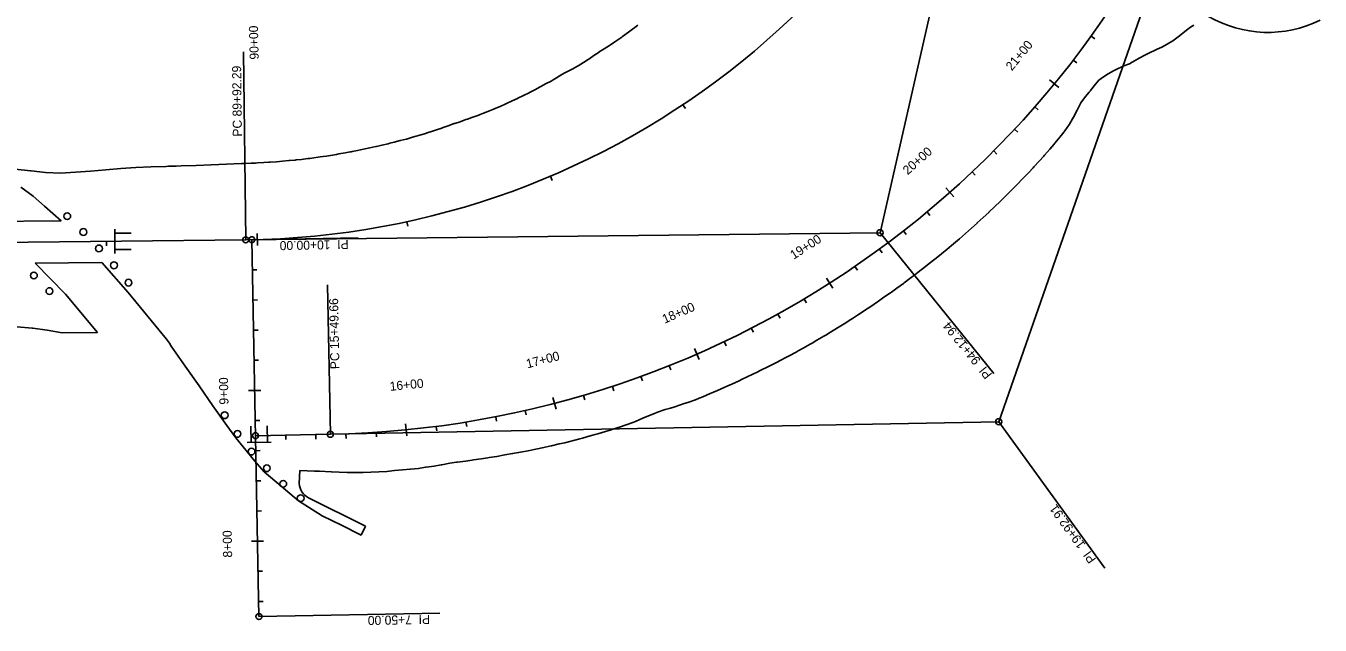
# Model space of a CAD drawing. Extents: x 1710760 to 1712674, y 548603 to 551129.
# Drawn here: x 1711587 to 1712445, y 548957 to 549354 of the extents above; entities that cross this region are included whole.
import ezdxf

# ---------------------------------------------------------------- set-up
doc = ezdxf.new("R2010")
doc.units = 0
for name, color, linetype in [('R_Horz Alg', 7, 'Continuous'), ('R_Horz Alg Annot', 7, 'Continuous'), ('R_MOT', 7, 'Continuous')]:
    doc.layers.add(name, color=color, linetype=linetype)

msp = doc.modelspace()

# ---------------------------------------------------------------- linework, layer by layer
at = {"layer": 'R_Horz Alg'}
for p, q in [((1711391.77, 549208.53), (1711733, 549212.35)), ((1711391.77, 549208.53), (1711733, 549212.35)), ((1711741.76, 548962.46), (1711737.05, 549212.41)), ((1711739.5, 549082.44), (1711789.16, 549083.37))]:
    msp.add_line(p, q, dxfattribs=at)
for centre, radius, start, end in [((1711727.02, 549745.3), 532.98, 270.64281, 347.20664), ((1711727.02, 549745.3), 532.98, 270.64281, 347.20664), ((1711777.17, 549719.88), 636.62, 271.07865, 340.7734)]:
    msp.add_arc(centre, radius, start, end, dxfattribs=at)
at = {"layer": 'R_Horz Alg Annot'}
for p, q in [((1712153.63, 549217.07), (1712246.77, 549627.28)), ((1712153.63, 549217.07), (1712246.77, 549627.28)), ((1712232.32, 549091.72), (1712378.29, 549510.24)), ((1711733, 549212.35), (1712153.63, 549217.07)), ((1711733, 549212.35), (1712153.63, 549217.07)), ((1711737.05, 549212.41), (1711807.64, 549213.74)), ((1711789.16, 549083.37), (1712232.32, 549091.72))]:
    msp.add_line(p, q, dxfattribs=at)
for points in [[(1712296, 549345.81), (1712293.57, 549347.56)], [(1711733, 549212.35), (1711731.6, 549337.05)], [(1712284, 549329.7), (1712281.62, 549331.53)], [(1712266.08, 549318.41), (1712272.26, 549313.34)], [(1712024.58, 549299.5), (1712022.91, 549302)], [(1712258.5, 549298.64), (1712256.24, 549300.62)], [(1712245.03, 549283.73), (1712242.83, 549285.78)], [(1712231.1, 549269.25), (1712228.97, 549271.37)], [(1711936.2, 549251.82), (1711935.03, 549254.59)], [(1712216.72, 549255.22), (1712214.66, 549257.4)], [(1712197.26, 549246.87), (1712202.57, 549240.89)], [(1712186.68, 549228.53), (1712184.76, 549230.84)], [(1711840.48, 549221.47), (1711839.85, 549224.4)], [(1711640.75, 549208.32), (1711640.71, 549211.32)], [(1711740.6, 549216.49), (1711740.81, 549208.5)], [(1712153.63, 549217.07), (1712229.02, 549123.72)], [(1712171.04, 549215.91), (1712169.19, 549218.28)], [(1712155.02, 549203.79), (1712153.24, 549206.21)], [(1712138.62, 549192.18), (1712136.92, 549194.65)], [(1711740.43, 549192.47), (1711737.43, 549192.42)], [(1712118.09, 549186.98), (1712122.4, 549180.24)], [(1711789.16, 549083.37), (1711787.29, 549182.55)], [(1711740.81, 549172.48), (1711737.81, 549172.42)], [(1712104.77, 549170.52), (1712103.23, 549173.1)], [(1712087.35, 549160.5), (1712085.9, 549163.13)], [(1711741.18, 549152.48), (1711738.18, 549152.43)], [(1712069.63, 549151.04), (1712068.26, 549153.7)], [(1712051.62, 549142.13), (1712050.33, 549144.84)], [(1712030.53, 549140.21), (1712033.74, 549132.88)], [(1711741.56, 549132.49), (1711738.56, 549132.43)], [(1712014.8, 549126.04), (1712013.68, 549128.82)], [(1711996.03, 549118.87), (1711995, 549121.69)], [(1711734.94, 549112.36), (1711742.94, 549112.51)], [(1711936.73, 549107.71), (1711938.75, 549099.97)], [(1711957.86, 549106.31), (1711957.01, 549109.19)], [(1711977.04, 549112.29), (1711976.11, 549115.14)], [(1711918.98, 549096.18), (1711918.31, 549099.1)], [(1711742.31, 549092.49), (1711739.31, 549092.44)], [(1711839, 549090.29), (1711839.79, 549082.33)], [(1711879.53, 549088.5), (1711879.05, 549091.47)], [(1711899.32, 549092.03), (1711898.74, 549094.98)], [(1712232.32, 549091.72), (1712302.73, 548994.54)], [(1711759.55, 549079.82), (1711759.5, 549082.81)], [(1711779.55, 549080.19), (1711779.49, 549083.19)], [(1711799.59, 549080.65), (1711799.49, 549083.65)], [(1711819.66, 549081.67), (1711819.46, 549084.67)], [(1711859.65, 549085.6), (1711859.26, 549088.58)], [(1711742.69, 549072.5), (1711739.69, 549072.44)], [(1711743.07, 549052.5), (1711740.07, 549052.44)], [(1711743.44, 549032.5), (1711740.44, 549032.45)], [(1711736.82, 549012.38), (1711744.82, 549012.53)], [(1711744.2, 548992.51), (1711741.2, 548992.45)], [(1711744.57, 548972.51), (1711741.57, 548972.46)], [(1711741.76, 548962.46), (1711861.74, 548964.72)]]:
    msp.add_lwpolyline(points, dxfattribs=at)
for centre in [(1712153.63, 549217.07), (1712153.63, 549217.07), (1711733, 549212.35), (1711733, 549212.35), (1711737.05, 549212.41), (1712232.32, 549091.72), (1711739.5, 549082.44), (1711789.16, 549083.37), (1711741.76, 548962.46)]:
    msp.add_circle(centre, 2, dxfattribs=at)
at = {"layer": 'R_MOT'}
for p, q in [((1711646.17, 549219.38), (1711646.17, 549203.38)), ((1711657.09, 549216.74), (1711646.17, 549216.74)), ((1711657.09, 549205.88), (1711646.17, 549205.88)), ((1711736.33, 549088.77), (1711736.54, 549077.85)), ((1711747.19, 549088.97), (1711747.4, 549078.05)), ((1711733.9, 549077.8), (1711749.9, 549078.1)), ((1711768.79, 549059.42), (1711768.48, 549050.73)), ((1711774.61, 549041.29), (1711812.49, 549022.46)), ((1711812.49, 549022.46), (1711809.54, 549016.53))]:
    msp.add_line(p, q, dxfattribs=at)
for points in [[(1711580.17, 549259.31), (1711590.19, 549258.2), (1711590.77, 549258.15), (1711600.2, 549257.08), (1711610.21, 549256.49), (1711620.2, 549257.29), (1711630.19, 549257.9), (1711640.18, 549258.81), (1711650.17, 549259.58), (1711660.16, 549260.43), (1711670.16, 549260.81), (1711680.16, 549261.06), (1711681.91, 549261.12), (1711686.83, 549261.29), (1711690.16, 549261.41), (1711700.15, 549261.77), (1711710.15, 549262.13), (1711720.15, 549262.52), (1711730.14, 549262.93), (1711732.43, 549263), (1711736.62, 549263.16), (1711739.4, 549263.29), (1711740.8, 549263.35), (1711744.97, 549263.58), (1711748.44, 549263.79), (1711749.15, 549263.84), (1711753.32, 549264.15), (1711757.45, 549264.49), (1711757.49, 549264.49), (1711761.65, 549264.88), (1711762, 549264.91), (1711765.81, 549265.3), (1711766.45, 549265.37), (1711766.45, 549265.37), (1711769.97, 549265.76), (1711774.11, 549266.25), (1711775.42, 549266.42), (1711778.26, 549266.79), (1711781.12, 549267.18), (1711782.4, 549267.36), (1711784.37, 549267.65), (1711786.53, 549267.97), (1711790.65, 549268.62), (1711793.29, 549269.06), (1711794.77, 549269.31), (1711798.88, 549270.04), (1711802.17, 549270.65), (1711802.98, 549270.8), (1711803.65, 549270.93), (1711807.07, 549271.6), (1711811.02, 549272.4), (1711811.16, 549272.43), (1711815.24, 549273.3), (1711819.31, 549274.2), (1711819.82, 549274.32), (1711823.36, 549275.14), (1711827.41, 549276.12), (1711828.58, 549276.41), (1711831.45, 549277.14), (1711835.48, 549278.19), (1711837.3, 549278.68), (1711839.51, 549279.24), (1711843.52, 549280.36), (1711845.97, 549281.07), (1711847.51, 549281.53), (1711851.49, 549282.74), (1711854.57, 549283.7), (1711855.46, 549283.96), (1711859.41, 549285.27), (1711863.1, 549286.53), (1711863.34, 549286.62), (1711867.26, 549288.01), (1711871.17, 549289.43), (1711871.56, 549289.56), (1711875.1, 549290.74), (1711879.03, 549292.09), (1711880.05, 549292.45), (1711882.93, 549293.47), (1711886.82, 549294.92), (1711888.47, 549295.55), (1711890.69, 549296.4), (1711894.55, 549297.93), (1711896.81, 549298.85), (1711898.39, 549299.5), (1711902.2, 549301.14), (1711905.04, 549302.39), (1711905.99, 549302.82), (1711909.76, 549304.52), (1711913.19, 549306.12), (1711913.52, 549306.27), (1711917.23, 549308.11), (1711920.93, 549309.97), (1711921.21, 549310.11), (1711924.62, 549311.85), (1711928.28, 549313.78), (1711929.14, 549314.26), (1711931.89, 549315.81), (1711935.56, 549317.71), (1711936.97, 549318.57), (1711939.09, 549319.88), (1711942.6, 549322.08), (1711944.65, 549323.15), (1711945.44, 549323.55), (1711946.26, 549323.97), (1711949.96, 549325.78), (1711952.53, 549327.3), (1711953.51, 549327.89), (1711957.03, 549330.04), (1711960.13, 549331.97), (1711960.53, 549332.23), (1711963.89, 549334.63), (1711967.31, 549336.94), (1711967.47, 549337.04), (1711970.79, 549339.12), (1711974.24, 549341.35), (1711974.96, 549341.83), (1711977.66, 549343.64), (1711981.05, 549345.97), (1711982.3, 549346.85), (1711982.92, 549347.28), (1711984.41, 549348.34), (1711987.74, 549350.74), (1711989.51, 549352.04), (1711991.04, 549353.18), (1711993.06, 549354.71)], [(1712361.79, 549354.84), (1712359.36, 549353.38), (1712356.88, 549351.47), (1712354.33, 549349.53), (1712352.36, 549347.88), (1712352.18, 549347.73), (1712350.48, 549346.27), (1712347.83, 549344.34), (1712342.51, 549341.37), (1712340.41, 549340.1), (1712337.3, 549338.82), (1712336.91, 549338.65), (1712331.3, 549335.98), (1712329.2, 549334.9), (1712325.98, 549333.17), (1712320.89, 549330.25), (1712319.09, 549329.16), (1712315.27, 549327.77), (1712309.79, 549325.24), (1712308.05, 549324.3), (1712305.23, 549322.69), (1712304.78, 549322.41), (1712301.14, 549320.06), (1712300.13, 549319.36), (1712298.79, 549318.31), (1712298.76, 549318.27), (1712296.54, 549315.52), (1712293.23, 549311.47), (1712293.07, 549311.27), (1712292.25, 549310.3), (1712289.85, 549307.47), (1712286.81, 549303.2), (1712286.15, 549301.93), (1712284.32, 549298.46), (1712281.78, 549293.75), (1712281.15, 549292.61), (1712279.21, 549289.04), (1712276.24, 549284.65), (1712275.52, 549283.75), (1712272.93, 549280.54), (1712269.59, 549276.46), (1712268.94, 549275.67), (1712266.22, 549272.41), (1712262.74, 549268.45), (1712262.14, 549267.78), (1712259.19, 549264.55), (1712255.61, 549260.68), (1712255.09, 549260.11), (1712252, 549256.83), (1712248.36, 549253.02), (1712247.92, 549252.55), (1712244.69, 549249.23), (1712240.98, 549245.48), (1712240.62, 549245.12), (1712237.24, 549241.76), (1712233.48, 549238.06), (1712233.2, 549237.79), (1712229.68, 549234.4), (1712225.85, 549230.77), (1712225.66, 549230.59), (1712221.99, 549227.17), (1712218.11, 549223.59), (1712218.01, 549223.51), (1712214.21, 549220.03), (1712210.25, 549216.54), (1712210.25, 549216.54), (1712206.25, 549213.09), (1712202.36, 549209.71), (1712202.27, 549209.63), (1712198.21, 549206.25), (1712194.31, 549203.08), (1712194.11, 549202.92), (1712189.99, 549199.62), (1712186.16, 549196.57), (1712185.86, 549196.33), (1712181.72, 549193.06), (1712177.92, 549190.17), (1712177.51, 549189.86), (1712173.3, 549186.68), (1712169.59, 549183.88), (1712169.08, 549183.5), (1712164.83, 549180.37), (1712161.17, 549177.72), (1712160.54, 549177.28), (1712156.21, 549174.25), (1712152.62, 549171.73), (1712151.89, 549171.22), (1712147.54, 549168.23), (1712143.97, 549165.89), (1712143.11, 549165.34), (1712138.71, 549162.42), (1712135.26, 549160.15), (1712134.29, 549159.53), (1712129.83, 549156.7), (1712126.44, 549154.56), (1712125.36, 549153.88), (1712120.87, 549151.1), (1712117.56, 549149.08), (1712116.35, 549148.36), (1712111.79, 549145.7), (1712108.54, 549143.83), (1712107.2, 549143.07), (1712102.6, 549140.47), (1712099.43, 549138.72), (1712097.98, 549137.92), (1712093.33, 549135.4), (1712090.25, 549133.76), (1712088.66, 549132.93), (1712083.97, 549130.49), (1712080.94, 549129.04), (1712079.23, 549128.17), (1712074.5, 549125.81), (1712071.6, 549124.39), (1712069.77, 549123.47), (1712065.02, 549121.16), (1712062.21, 549119.83), (1712060.24, 549118.91), (1712055.44, 549116.71), (1712052.73, 549115.47), (1712050.63, 549114.53), (1712045.8, 549112.4), (1712043.18, 549111.27), (1712040.95, 549110.31), (1712036.09, 549108.25), (1712033.57, 549107.21), (1712031.18, 549106.29), (1712026.2, 549104.53), (1712023.74, 549103.69), (1712021.21, 549102.8), (1712016.17, 549101.2), (1712013.8, 549100.51), (1712011.08, 549099.74), (1712006.13, 549097.94), (1712003.96, 549097.08), (1712001.23, 549096.01), (1711996.35, 549094), (1711994.32, 549093.11), (1711991.5, 549091.88), (1711986.58, 549089.97), (1711984.6, 549089.33), (1711981.55, 549088.35), (1711976.52, 549086.76), (1711974.65, 549086.19), (1711971.47, 549085.22), (1711966.41, 549083.72), (1711964.66, 549083.22), (1711961.34, 549082.27), (1711956.26, 549080.85), (1711954.62, 549080.4), (1711951.16, 549079.48), (1711946.06, 549078.15), (1711944.53, 549077.79), (1711940.92, 549076.96), (1711935.78, 549075.77), (1711934.38, 549075.44), (1711930.64, 549074.59), (1711925.47, 549073.53), (1711924.19, 549073.27), (1711920.3, 549072.49), (1711915.13, 549071.46), (1711913.97, 549071.24), (1711909.95, 549070.51), (1711904.75, 549069.62), (1711903.71, 549069.44), (1711899.56, 549068.72), (1711894.36, 549067.9), (1711893.44, 549067.76), (1711889.15, 549067.12), (1711883.93, 549066.37), (1711883.14, 549066.25), (1711878.72, 549065.61), (1711873.51, 549064.89), (1711872.84, 549064.8), (1711868.3, 549064.14), (1711863.12, 549063.15), (1711862.58, 549063.05), (1711857.92, 549062.3), (1711852.71, 549061.53), (1711852.29, 549061.46), (1711847.49, 549060.75), (1711842.25, 549060.22), (1711841.96, 549060.19), (1711837, 549059.74), (1711831.75, 549059.24), (1711831.59, 549059.23), (1711826.51, 549058.73), (1711821.25, 549058.4), (1711821.21, 549058.4), (1711815.98, 549058.16), (1711810.8, 549058.03), (1711810.71, 549058.03), (1711805.44, 549057.96), (1711800.39, 549057.93), (1711800.17, 549057.94), (1711794.9, 549058.15), (1711789.98, 549058.38), (1711789.63, 549058.4), (1711781.98, 549058.81), (1711779.95, 549058.91), (1711778.61, 549058.99), (1711768.79, 549059.42)], [(1711560.71, 549224.42), (1711610.62, 549224.98), (1711599.47, 549234.71), (1711591.96, 549241.26), (1711583.97, 549247.29)], [(1711809.54, 549016.53), (1711809.18, 549016.65), (1711796.41, 549023), (1711783.63, 549029.35), (1711768, 549039.3), (1711756.58, 549048.87), (1711745.16, 549058.45), (1711738.97, 549065.42), (1711726.34, 549080.94), (1711720.47, 549089.12), (1711711.27, 549102.3), (1711702.07, 549115.47), (1711692.86, 549128.64), (1711683.66, 549141.82), (1711682.42, 549143.88), (1711680.5, 549146.55), (1711655.07, 549177.46), (1711637.58, 549197.28), (1711593.46, 549196.79)], [(1711593.46, 549196.79), (1711613.53, 549176.4), (1711634.73, 549150.92)], [(1711634.73, 549150.92), (1711611.39, 549150.72), (1711601.37, 549152.37), (1711591.94, 549153.69), (1711591.36, 549153.76), (1711581.35, 549154.67)]]:
    msp.add_lwpolyline(points, dxfattribs=at)
for centre in [(1711614.65, 549228.05), (1711625.35, 549217.54), (1711635.69, 549206.67), (1711645.66, 549195.47), (1711592.54, 549188.72), (1711655.26, 549183.94), (1711602.86, 549178.35), (1711719.05, 549095.99), (1711727.54, 549083.62), (1711736.87, 549071.89), (1711747, 549060.83), (1711757.89, 549050.51), (1711769.46, 549040.98)]:
    msp.add_circle(centre, 2.25, dxfattribs=at)
for centre, radius, start, end in [((1712410.8, 549427.94), 78, 239.65233, 296.34238), ((1711779.54, 549051.21), 11.07, 182.45955, 243.55778)]:
    msp.add_arc(centre, radius, start, end, dxfattribs=at)

# ---------------------------------------------------------------- texts
at = {"layer": 'R_Horz Alg Annot'}
for s, rotation, p in [('90+00', 91.47143, (1711741.66, 549332.02)), ('21+00', 50.60881, (1712241.01, 549324.12)), ('PC 89+92.29', 90.64281, (1711730.47, 549280.86)), ('20+00', 41.60881, (1712171.94, 549255.14)), ('PI  10+00.00', 181.07865, (1711801.19, 549212.35)), ('19+00', 32.60881, (1712096.38, 549199.13)), ('PC 15+49.66', 91.07865, (1711795.15, 549126.61)), ('18+00', 23.60881, (1712010.78, 549156.68)), ('PI  94+12.94', 128.92472, (1712228.24, 549123.09)), ('17+00', 14.60881, (1711919.8, 549127.07)), ('9+00', 91.07865, (1711721.59, 549103.12)), ('16+00', 5.60881, (1711828.77, 549112.14)), ('PI  19+92.91', 125.92603, (1712297.21, 549000.46)), ('8+00', 91.07865, (1711724.02, 549001.62)), ('PI  7+50.00', 181.07865, (1711855.17, 548963.59))]:
    msp.add_text(s, height=6, rotation=rotation, dxfattribs=at).set_placement(p)

doc.saveas('drawing.dxf')
